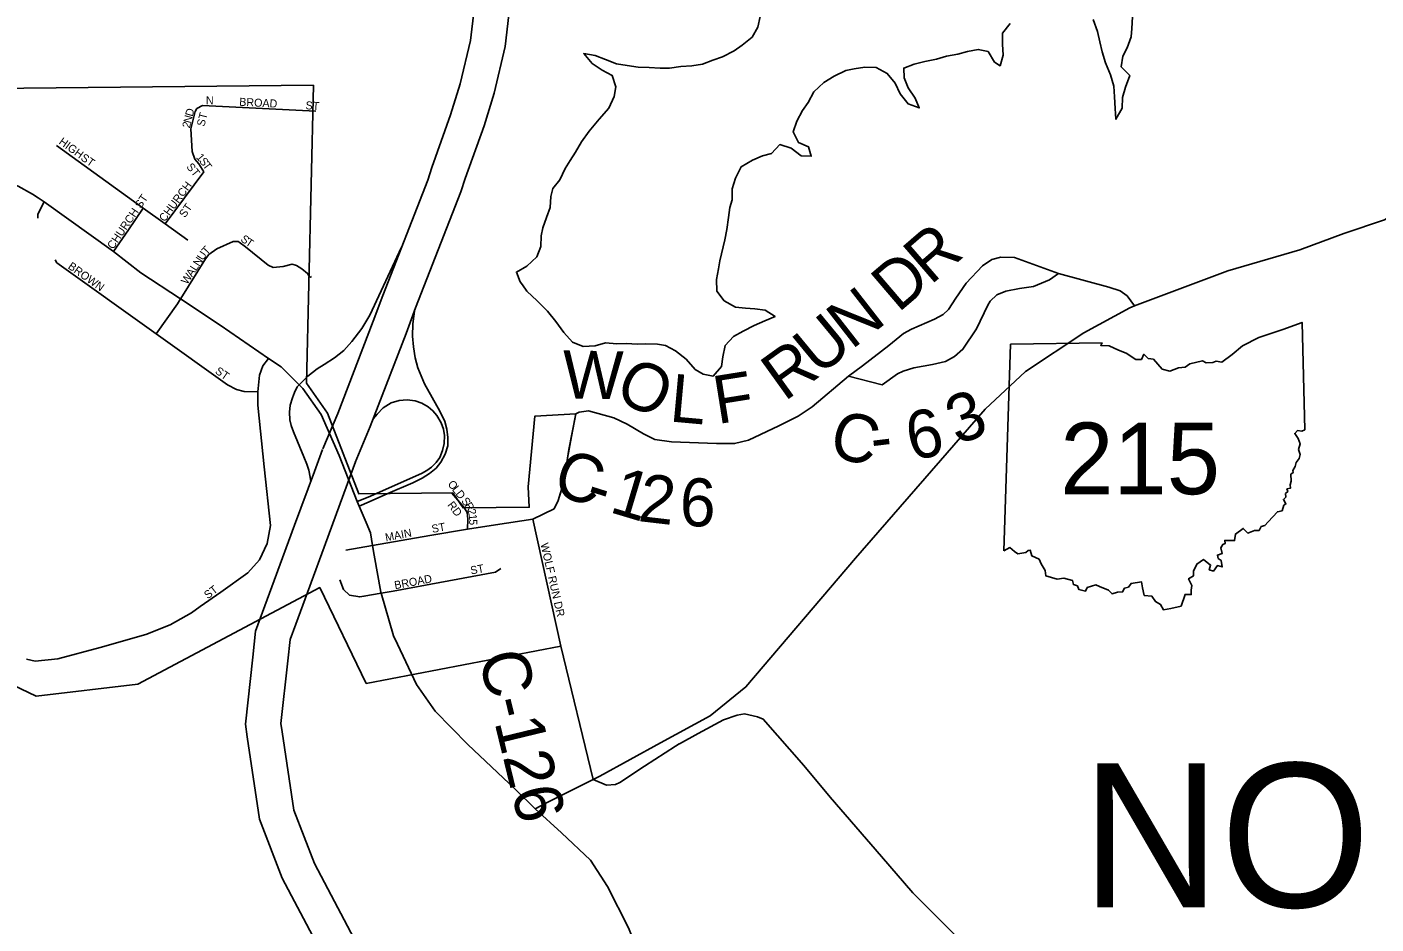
# Model space of a CAD drawing. Extents: x 0 to 34, y 0 to 22.
# Drawn here: x 25.646 to 27.239, y 10.21 to 11.27 of the extents above; entities that cross this region are included whole.
import ezdxf

# ---------------------------------------------------------------- set-up
doc = ezdxf.new("R2010")
doc.units = 0
for name, color, linetype in [('Default', 7, 'Continuous'), ('GM_X_City_Street', 7, 'Continuous'), ('GM_X_City_Street_Text', 7, 'Continuous'), ('GM_X_Corporation', 7, 'Continuous'), ('GM_X_County_Road_Text', 7, 'Continuous'), ('GM_X_Interchange_Ramps', 7, 'Continuous'), ('GM_X_Major_River', 7, 'Continuous'), ('GM_X_State_Route', 7, 'Continuous'), ('GM_X_Township_Text', 7, 'Continuous')]:
    doc.layers.add(name, color=color, linetype=linetype)

msp = doc.modelspace()

# ---------------------------------------------------------------- linework, layer by layer
at = {"layer": 'Default'}
msp.add_line((26.7992, 10.6513), (26.807, 10.8953), dxfattribs=at)
for points in [[(26.6156, 10.8577), (26.6156, 10.8577), (26.6322, 10.8698), (26.6632, 10.8937), (26.6805, 10.9081), (26.69, 10.913), (26.7172, 10.9248), (26.7274, 10.9305), (26.7338, 10.9362), (26.7425, 10.9498), (26.7546, 10.9673), (26.7738, 10.9881), (26.7851, 10.9953), (26.7957, 10.9983), (26.8116, 10.9976), (26.8637, 10.9789)], [(26.6156, 10.8577), (26.6553, 10.8475), (26.6734, 10.8604), (26.6802, 10.8634), (26.6927, 10.8676), (26.715, 10.8714), (26.7304, 10.8749), (26.741, 10.8809), (26.7508, 10.8893), (26.7667, 10.9135), (26.7803, 10.9416), (26.7829, 10.9461), (26.7908, 10.9537), (26.8014, 10.9579), (26.8177, 10.9613), (26.8343, 10.9636), (26.8532, 10.9712), (26.8637, 10.9789)], [(26.8637, 10.9789), (26.9231, 10.9626), (26.9367, 10.9584), (26.9446, 10.9524), (26.9534, 10.9405)], [(26.807, 10.8953), (26.9152, 10.8969), (26.9135, 10.8939), (26.9237, 10.8933), (26.9346, 10.8881), (26.9437, 10.8848), (26.9549, 10.8771), (26.9616, 10.8771), (26.9645, 10.8835), (26.9696, 10.8786), (26.9757, 10.8777), (26.9863, 10.866), (26.995, 10.8635), (27.0055, 10.8675), (27.0132, 10.8682), (27.0189, 10.8721), (27.0338, 10.8755), (27.038, 10.8735), (27.0458, 10.8739), (27.0498, 10.8754), (27.0566, 10.874), (27.0686, 10.883), (27.0811, 10.8934), (27.1002, 10.9033), (27.1287, 10.9126), (27.1513, 10.921), (27.1546, 10.7943)], [(26.2937, 10.8129), (26.2937, 10.8129), (26.2978, 10.8152), (26.3088, 10.8167), (26.3386, 10.8085), (26.3545, 10.8009), (26.3738, 10.7896), (26.387, 10.7828), (26.4067, 10.7798), (26.46, 10.778), (26.4811, 10.778), (26.4977, 10.7818), (26.5336, 10.7989), (26.5563, 10.8103), (26.5729, 10.8213), (26.6156, 10.8577)], [(27.1546, 10.7943), (27.1512, 10.7926), (27.1461, 10.7934), (27.1426, 10.7899), (27.1469, 10.7839), (27.1489, 10.7776), (27.1471, 10.7708), (27.1489, 10.7651), (27.1477, 10.7603), (27.1445, 10.7555), (27.1433, 10.751), (27.1405, 10.7463), (27.1407, 10.7436), (27.1381, 10.7416), (27.1386, 10.7336), (27.1373, 10.7292), (27.1377, 10.7254), (27.1334, 10.7244), (27.1344, 10.7213), (27.1317, 10.7189), (27.1323, 10.7147), (27.1292, 10.712), (27.1322, 10.7067), (27.1298, 10.7051), (27.1278, 10.6986), (27.1222, 10.6973), (27.1113, 10.6855), (27.1074, 10.681), (27.1031, 10.6799), (27.1006, 10.6753), (27.0953, 10.6753), (27.0871, 10.6721), (27.0819, 10.6776), (27.0727, 10.671), (27.0716, 10.6634), (27.06, 10.6636), (27.0604, 10.6598), (27.0578, 10.6587), (27.0555, 10.6548), (27.0568, 10.648), (27.0514, 10.6462), (27.0521, 10.6422), (27.0556, 10.6399), (27.0571, 10.6322), (27.0513, 10.6337), (27.0466, 10.6273), (27.0417, 10.6289), (27.0433, 10.6343), (27.035, 10.6408), (27.0272, 10.6356), (27.0232, 10.6272), (27.0231, 10.6216), (27.0173, 10.6182), (27.0211, 10.6103), (27.0203, 10.6048), (27.0205, 10.5996), (27.0132, 10.5998), (27.0087, 10.5858)], [(27.0087, 10.5858), (26.9962, 10.5831), (26.9875, 10.5815), (26.9843, 10.5879), (26.9781, 10.5913), (26.974, 10.5976), (26.965, 10.5985), (26.9628, 10.6073), (26.9618, 10.6144), (26.9495, 10.6127), (26.9462, 10.6083), (26.9418, 10.6071), (26.9393, 10.6027), (26.9333, 10.6024), (26.9269, 10.6003), (26.9227, 10.6046), (26.9123, 10.6089), (26.9076, 10.6112), (26.8977, 10.6077), (26.8956, 10.6036), (26.8879, 10.6054), (26.886, 10.61), (26.8813, 10.6114), (26.8802, 10.6162), (26.8701, 10.6188), (26.8623, 10.6178), (26.8487, 10.6217), (26.8478, 10.6281), (26.8432, 10.6359), (26.8408, 10.6413), (26.8322, 10.6454), (26.8304, 10.6519), (26.8277, 10.6517), (26.8251, 10.6491), (26.8155, 10.6478), (26.8117, 10.6505), (26.8063, 10.655), (26.7992, 10.6513)], [(26.3144, 10.3811), (26.276, 10.5386)], [(26.7556, 10.1835), (26.6917, 10.2473), (26.6546, 10.29), (26.5941, 10.36), (26.5631, 10.3974), (26.515, 10.4522), (26.5082, 10.4552), (26.4931, 10.4586), (26.4844, 10.4571), (26.4682, 10.4514), (26.4383, 10.4354), (26.4162, 10.4232)], [(26.4162, 10.4232), (26.4158, 10.423), (26.4115, 10.4206), (26.3749, 10.3967), (26.3458, 10.3774), (26.3405, 10.3751), (26.3299, 10.3743), (26.3144, 10.3811)]]:
    msp.add_lwpolyline(points, dxfattribs=at)
at = {"layer": 'GM_X_City_Street'}
for points in [[(25.8438, 11.1141), (25.8407, 11.1231), (25.8392, 11.1496), (25.8442, 11.1701), (25.8461, 11.1739)], [(25.8461, 11.1739), (25.8528, 11.1774), (25.9867, 11.1705)], [(25.6805, 11.1301), (25.7829, 11.0562), (25.8088, 11.0376), (25.8356, 11.0182)], [(25.8546, 11.0991), (25.8484, 11.1085), (25.8438, 11.1141)], [(25.8088, 11.0376), (25.8546, 11.0991)], [(25.6585, 11.0443), (25.6585, 11.0488), (25.666, 11.0634)], [(25.7654, 11.0305), (25.7829, 11.0562)], [(25.7479, 11.0048), (25.7654, 11.0305), (25.7654, 11.0305)], [(25.8272, 10.9493), (25.8563, 10.9962), (25.8604, 11.0012), (25.8697, 11.0081), (25.8889, 11.0167), (25.8949, 11.0168), (25.8961, 11.0159)], [(25.8961, 11.0159), (25.8963, 11.0158), (25.9037, 11.0104), (25.9304, 10.9888), (25.9365, 10.9859), (25.9482, 10.9872), (25.9587, 10.99), (25.9637, 10.9885), (25.9701, 10.9845), (25.977, 10.9789), (25.9794, 10.9748), (25.9806, 10.9745), (25.9814, 10.9752)], [(25.6788, 10.995), (25.6807, 10.9916), (25.7981, 10.9075), (25.8824, 10.8474), (25.893, 10.8419), (25.9021, 10.8394), (25.9181, 10.8392)], [(25.7981, 10.9075), (25.8234, 10.9432), (25.8269, 10.9488), (25.827, 10.949), (25.8272, 10.9493)], [(25.6451, 10.5232), (25.6553, 10.5209), (25.6821, 10.5236), (25.732, 10.537), (25.786, 10.5522), (25.8147, 10.5636), (25.84, 10.578), (25.8502, 10.5856), (25.8744, 10.6023), (25.9065, 10.6254), (25.9201, 10.6406), (25.9291, 10.6599), (25.9333, 10.6811), (25.9256, 10.7503), (25.9184, 10.8234), (25.9181, 10.8392), (25.9203, 10.8589), (25.924, 10.8699), (25.9309, 10.8786)], [(26.2431, 10.6885), (26.2681, 10.701), (26.2728, 10.7108), (26.2748, 10.7171), (26.2798, 10.7332), (26.284, 10.7605), (26.2885, 10.7862), (26.2937, 10.8129)], [(26.1659, 10.6768), (26.1662, 10.6885), (26.1653, 10.6964), (26.1615, 10.7028), (26.1473, 10.7193)], [(26.1214, 10.6692), (26.1659, 10.6768), (26.1988, 10.6818)], [(26.1988, 10.6818), (26.2431, 10.6885)], [(26.276, 10.5386), (26.2431, 10.6885)], [(26.022, 10.6521), (26.0538, 10.6576), (26.1214, 10.6692)], [(26.0432, 10.5976), (26.0434, 10.5976), (26.0637, 10.6011), (26.0781, 10.6037), (26.1987, 10.6261), (26.2051, 10.6303)], [(26.0149, 10.6169), (26.0192, 10.6056), (26.0265, 10.5988), (26.0386, 10.5967), (26.0432, 10.5976)]]:
    msp.add_lwpolyline(points, dxfattribs=at)
at = {"layer": 'GM_X_Corporation'}
msp.add_lwpolyline([(25.9839, 11.2013), (25.9758, 10.8493), (26.0003, 10.8138), (26.0373, 10.7186), (26.1483, 10.7197), (26.1605, 10.702), (26.2388, 10.7027), (26.2375, 10.7269), (26.2453, 10.8102), (26.2937, 10.8129), (26.2856, 10.771), (26.2797, 10.7327), (26.2728, 10.7107), (26.268, 10.7008), (26.2431, 10.6885), (26.276, 10.5386), (26.0463, 10.4945), (25.9914, 10.6078), (25.7766, 10.4938), (25.6566, 10.4793), (25.5936, 10.5094), (25.478, 10.5119), (25.4897, 11.1961)], close=True, dxfattribs=at)
at = {"layer": 'GM_X_Interchange_Ramps'}
for points in [[(26.0879, 11.0099), (26.0503, 10.9298), (26.041, 10.9139), (26.0294, 10.8985), (26.0196, 10.8879), (26.0086, 10.8794), (25.9967, 10.8712), (25.9882, 10.8663), (25.9771, 10.8577), (25.9669, 10.8474)], [(26.0379, 10.704), (26.0497, 10.709), (26.0716, 10.7188), (26.1012, 10.7316), (26.1121, 10.7371), (26.121, 10.7426), (26.1289, 10.749), (26.1345, 10.756), (26.1396, 10.7653), (26.1426, 10.7754), (26.1426, 10.7852), (26.1416, 10.795), (26.139, 10.804), (26.133, 10.8164), (26.1151, 10.8486), (26.1109, 10.858), (26.1072, 10.8676), (26.1041, 10.8794), (26.1022, 10.8922), (26.101, 10.9047), (26.1013, 10.9193), (26.1031, 10.9344)], [(25.9669, 10.8474), (25.9646, 10.8451), (25.9615, 10.8382), (25.9593, 10.8321), (25.9566, 10.8232), (25.9555, 10.8151), (25.956, 10.8059), (25.9577, 10.7991), (25.9605, 10.7917), (25.9727, 10.7623), (25.976, 10.7536), (25.9783, 10.7465), (25.9802, 10.7381), (25.9807, 10.7333)], [(26.0546, 10.8071), (26.059, 10.8128), (26.0663, 10.8203), (26.0758, 10.826), (26.0852, 10.829), (26.0944, 10.8295), (26.1039, 10.8283), (26.1118, 10.8255), (26.1194, 10.8212), (26.125, 10.8167), (26.1295, 10.8111), (26.1347, 10.8026), (26.1373, 10.7949), (26.1385, 10.7875), (26.1384, 10.7781), (26.1363, 10.7696), (26.1332, 10.7616), (26.1288, 10.7556), (26.1232, 10.7501), (26.1178, 10.7461), (26.1116, 10.7426), (26.0484, 10.7146), (26.0355, 10.7095)]]:
    msp.add_lwpolyline(points, dxfattribs=at)
at = {"layer": 'GM_X_Major_River'}
for points in [[(26.5115, 11.2826), (26.5086, 11.27), (26.5019, 11.2582), (26.4903, 11.2486), (26.4806, 11.2421), (26.467, 11.2348), (26.4554, 11.2309), (26.4433, 11.2262), (26.4309, 11.2242), (26.4176, 11.2236), (26.4044, 11.2216), (26.3935, 11.2215), (26.3802, 11.2221), (26.3674, 11.2227), (26.3545, 11.2245), (26.3417, 11.2266), (26.3288, 11.2318), (26.3166, 11.2365), (26.303, 11.2387), (26.3129, 11.227), (26.3247, 11.2192), (26.3365, 11.2129), (26.3408, 11.1993), (26.339, 11.188), (26.3327, 11.1743), (26.3212, 11.1613), (26.3096, 11.1472), (26.3003, 11.1346), (26.2932, 11.1224), (26.2869, 11.1125), (26.2813, 11.103), (26.2747, 11.0897), (26.2665, 11.0794), (26.2643, 11.0699), (26.2633, 11.057), (26.2589, 11.0452), (26.2548, 11.0327), (26.2527, 11.0232), (26.2524, 11.0107), (26.2476, 10.9986), (26.2357, 10.9875), (26.2236, 10.9805), (26.2279, 10.9692), (26.2307, 10.9653)], [(26.9045, 11.2789), (26.9096, 11.2649), (26.9124, 11.2525), (26.9151, 11.2408), (26.919, 11.2276), (26.9252, 11.2136), (26.9292, 11.2001), (26.93, 11.1876), (26.9306, 11.174), (26.9314, 11.1611), (26.9389, 11.1741), (26.9391, 11.1869), (26.9428, 11.1991), (26.9479, 11.2128), (26.9376, 11.2232), (26.9397, 11.2357), (26.9449, 11.2456), (26.9497, 11.2586), (26.9504, 11.2684), (26.951, 11.282)], [(26.7883, 11.2284), (26.7948, 11.2243), (26.7984, 11.2369), (26.7975, 11.2497), (26.7974, 11.263), (26.8067, 11.2744)], [(26.4689, 10.9465), (26.4604, 10.9581), (26.4599, 10.9717), (26.4624, 10.9843), (26.4638, 10.9937), (26.4696, 11.0188), (26.4721, 11.0309), (26.4739, 11.0449), (26.4757, 11.0567), (26.4782, 11.0661), (26.4785, 11.079), (26.4821, 11.0915), (26.4891, 11.1049), (26.5023, 11.1129), (26.514, 11.118), (26.5249, 11.1208), (26.5346, 11.1311), (26.5479, 11.1271), (26.5597, 11.1177), (26.5718, 11.1175), (26.5686, 11.1284), (26.5565, 11.1336), (26.5503, 11.1464), (26.5547, 11.1589), (26.5614, 11.1715), (26.5681, 11.181), (26.5748, 11.1936), (26.5867, 11.2047), (26.5988, 11.212), (26.6127, 11.2186), (26.6225, 11.2206), (26.6349, 11.2226), (26.6482, 11.2224), (26.6615, 11.2153), (26.671, 11.2037), (26.6768, 11.1913), (26.686, 11.1793), (26.6993, 11.1745), (26.6946, 11.1862), (26.6862, 11.1982), (26.6815, 11.2102), (26.681, 11.2216), (26.6931, 11.2263), (26.7059, 11.2294), (26.7195, 11.2322), (26.7315, 11.2358), (26.7447, 11.2382), (26.7564, 11.2413), (26.7689, 11.2437), (26.7806, 11.2412), (26.7883, 11.2284)], [(26.2307, 10.9653), (26.236, 10.958), (26.2482, 10.9464), (26.2604, 10.9344), (26.27, 10.922), (26.2795, 10.9092), (26.2899, 10.8976), (26.3024, 10.8925), (26.3164, 10.8934), (26.3288, 10.8969), (26.342, 10.8959), (26.3537, 10.8961), (26.3662, 10.8954), (26.3764, 10.8959), (26.39, 10.8953), (26.3995, 10.8939), (26.4116, 10.8876), (26.4242, 10.8775), (26.4345, 10.8655), (26.444, 10.86), (26.4558, 10.8574), (26.4659, 10.8689), (26.4673, 10.8806), (26.4701, 10.8939), (26.4799, 10.9046), (26.4915, 10.9108), (26.5043, 10.9174), (26.5171, 10.9228), (26.5291, 10.9282), (26.5173, 10.9357), (26.5052, 10.937), (26.4939, 10.9381), (26.4822, 10.9391), (26.4689, 10.9465)]]:
    msp.add_lwpolyline(points, dxfattribs=at)
at = {"layer": 'GM_X_State_Route'}
for p, q in [((25.985, 10.745), (25.9946, 10.7709)), ((26.024, 10.7306), (26.0336, 10.7565)), ((25.9617, 10.6817), (25.985, 10.745)), ((26.0007, 10.6673), (26.024, 10.7306)), ((25.9376, 10.6163), (25.9617, 10.6817)), ((25.9767, 10.6019), (26.0007, 10.6673)), ((25.9239, 10.5789), (25.9376, 10.6163)), ((25.9629, 10.5646), (25.9767, 10.6019))]:
    msp.add_line(p, q, dxfattribs=at)
for points in [[(25.9949, 10.7718), (26.0125, 10.8135), (26.0546, 10.9225), (26.0657, 10.953), (26.1189, 11.089), (26.1236, 11.1043), (26.1459, 11.1665), (26.1572, 11.2029), (26.1694, 11.2542), (26.1787, 11.3347), (26.1777, 11.4861), (26.1663, 11.7018), (26.1499, 11.9302), (26.1352, 12.1964), (26.1137, 12.5526), (26.0897, 12.974), (26.0747, 13.2305)], [(26.0332, 10.7556), (26.051, 10.798), (26.0935, 10.9079), (26.1046, 10.9383), (26.1581, 11.0753), (26.163, 11.0912), (26.1854, 11.1533), (26.1973, 11.192), (26.2104, 11.2469), (26.2203, 11.3325), (26.2193, 11.4873), (26.2078, 11.7044), (26.1914, 11.9329), (26.1767, 12.1988), (26.1552, 12.555), (26.1312, 12.9764), (26.1162, 13.2323)], [(26.2457, 10.3462), (26.2585, 10.353), (26.3144, 10.3811), (26.322, 10.3849), (26.3938, 10.4244), (26.4523, 10.4563), (26.4946, 10.4904), (26.624, 10.6426), (26.777, 10.8187), (26.8246, 10.8629), (26.8937, 10.9087), (26.9481, 10.9385), (26.9534, 10.9405), (27.0636, 10.982), (27.1485, 11.0069), (27.2007, 11.0261), (27.2487, 11.0423), (27.2786, 11.0614), (27.3842, 11.1566), (27.5211, 11.296)], [(25.6587, 11.0681), (25.652, 11.0725), (25.6354, 11.082), (25.6223, 11.0864), (25.601, 11.087), (25.5876, 11.0908), (25.5759, 11.0968), (25.5648, 11.106), (25.5569, 11.1172), (25.5521, 11.1303), (25.5496, 11.1455), (25.5506, 11.1796)], [(25.9309, 10.8786), (25.8739, 10.9178), (25.8269, 10.9488), (25.7801, 10.9795), (25.7479, 11.0048), (25.666, 11.0634), (25.6587, 11.0681)], [(26.0248, 10.7366), (26.0141, 10.7637), (25.9932, 10.8121), (25.9713, 10.8431), (25.9669, 10.8474), (25.9585, 10.8558), (25.9456, 10.8685), (25.9309, 10.8786)], [(26.0557, 10.6461), (26.0538, 10.6576), (26.0512, 10.6725), (26.0461, 10.6845), (26.0379, 10.704), (26.0355, 10.7095), (26.0248, 10.7366)], [(26.0928, 10.5202), (26.083, 10.541), (26.0785, 10.5507), (26.0637, 10.6011), (26.0633, 10.6023), (26.0557, 10.6461)], [(25.9122, 10.5257), (25.9155, 10.5561), (25.9239, 10.5789)], [(25.9535, 10.5212), (25.9563, 10.5465), (25.9629, 10.5646)], [(25.9058, 10.4314), (25.9036, 10.4463), (25.9122, 10.5257)], [(25.9469, 10.4375), (25.9455, 10.4471), (25.9535, 10.5212)], [(26.2457, 10.3462), (26.2222, 10.3696), (26.1663, 10.4222), (26.1277, 10.4618), (26.1054, 10.4932), (26.0928, 10.5202)], [(26.3457, 9.6259), (26.3244, 9.6791), (26.2863, 9.7773), (26.2391, 9.8739), (26.1898, 9.9475), (26.1069, 10.0851), (26.0437, 10.1703), (25.9851, 10.2816), (25.9607, 10.3449), (25.9469, 10.4375)], [(26.3071, 9.6104), (26.2857, 9.6638), (26.2481, 9.7607), (26.2029, 9.8531), (26.1547, 9.9252), (26.0723, 10.0619), (26.0083, 10.1481), (25.9471, 10.2644), (25.9203, 10.3342), (25.9058, 10.4314)], [(26.6155, 9.6437), (26.6136, 9.6569), (26.5965, 9.7412), (26.5809, 9.8044), (26.5567, 9.8509), (26.5356, 9.8752), (26.4861, 9.9447), (26.4462, 9.9919), (26.4184, 10.0357), (26.3925, 10.0841), (26.3823, 10.1152), (26.3734, 10.1453), (26.3702, 10.1564), (26.3626, 10.1893), (26.3558, 10.2056), (26.3312, 10.2548), (26.3111, 10.2858), (26.2767, 10.3179), (26.2457, 10.3462)]]:
    msp.add_lwpolyline(points, dxfattribs=at)

# ---------------------------------------------------------------- texts
at = {"layer": 'Default'}
msp.add_text('215', height=0.08462, dxfattribs=at).set_placement((26.8657, 10.7181))
at = {"layer": 'GM_X_City_Street_Text'}
for s, rotation, p in [('N', 0, (25.8569, 11.1788)), ('BROAD', 357.0909, (25.8961, 11.1771)), ('D', 74.0816, (25.8412, 11.1637)), ('ST', 75.9573, (25.8551, 11.152)), ('ST', 356.1879, (25.9743, 11.173)), ('2', 75.9335, (25.8378, 11.15)), ('N', 75.916, (25.8392, 11.1557)), ('HIGH', 324.0898, (25.6824, 11.1327)), ('ST', 325.3092, (25.7082, 11.1136)), ('1', 309.8056, (25.8448, 11.1159)), ('ST', 309.0829, (25.8333, 11.1047)), ('S', 307.7168, (25.8485, 11.1115)), ('T', 306.411, (25.8525, 11.1062)), ('CHURCH', 53.3211, (25.8082, 11.0392)), ('CHURCH ST', 55.904, (25.7474, 11.0067)), ('ST', 55.2978, (25.8322, 11.0441)), ('S', 322.7312, (25.897, 11.0179)), ('T', 46.3331, (25.8578, 11.0002)), ('T', 326.094, (25.9028, 11.0135)), ('BROWN', 324.4633, (25.6932, 10.9855)), ('N', 56.5811, (25.8489, 10.9866)), ('U', 56.5766, (25.8535, 10.9936)), ('W', 56.5757, (25.8347, 10.9651)), ('A', 56.5811, (25.8406, 10.9741)), ('L', 56.5752, (25.8452, 10.9811)), ('ST', 325.3092, (25.867, 10.8616)), ('O', 308.7281, (26.1418, 10.7299)), ('L', 308.7013, (26.147, 10.7235)), ('D', 308.7219, (26.1511, 10.7183)), ('RD', 307.4135, (26.1416, 10.7052)), ('S', 308.7281, (26.1579, 10.7098)), ('R', 302.4507, (26.1619, 10.7049)), ('2', 287.6353, (26.1656, 10.6991)), ('1', 275.4403, (26.1673, 10.6941)), ('MAIN', 10.7134, (26.0695, 10.6623)), ('ST', 10.6147, (26.1244, 10.6723)), ('5', 270.5932, (26.1678, 10.6885)), ('WOLF RUN DR', 282.8582, (26.2519, 10.6594)), ('ST', 10.6279, (26.1701, 10.6232)), ('ST', 37.5735, (25.8592, 10.5938)), ('BROAD', 10.6227, (26.0803, 10.6058))]:
    msp.add_text(s, height=0.00945, rotation=rotation, dxfattribs=at).set_placement(p)
at = {"layer": 'GM_X_County_Road_Text'}
for s, rotation, p in [('R', 40.8254, (26.7125, 10.9643)), ('D', 40.4787, (26.6742, 10.9316)), ('N', 37.9088, (26.6192, 10.8881)), ('U', 39.5671, (26.5811, 10.8566)), ('W', 358.8739, (26.2777, 10.8315)), ('R', 35.6808, (26.54, 10.8269)), ('O', 334.3277, (26.3372, 10.8316)), ('L', 354.7876, (26.4033, 10.8042)), ('F', 9.0926, (26.461, 10.8008)), ('3', 20.3601, (26.744, 10.776)), ('6', 11.6746, (26.6901, 10.7575)), ('C', 346.1465, (26.5907, 10.7637)), ('-', 6.9111, (26.6447, 10.7561)), ('C', 342.2019, (26.2642, 10.7191)), ('1', 343.3517, (26.3319, 10.6974)), ('2', 353.3579, (26.3661, 10.6865)), ('6', 358.2651, (26.4159, 10.6808)), ('-', 342.3963, (26.3023, 10.7042)), ('C-126', 283.6351, (26.1786, 10.5269))]:
    msp.add_text(s, height=0.0567, rotation=rotation, dxfattribs=at).set_placement(p)
at = {"layer": 'GM_X_Township_Text'}
msp.add_text('NOBLE', height=0.1701, rotation=0, dxfattribs=at).set_placement((26.8907, 10.2301))

doc.saveas('drawing.dxf')
